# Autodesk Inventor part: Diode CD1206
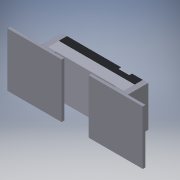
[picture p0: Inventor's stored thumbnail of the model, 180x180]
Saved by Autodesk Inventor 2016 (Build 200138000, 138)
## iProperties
Created: 2018-03
Part Number: Diode CD1206
Material: Générique
Document SubType Name: Modeling
Designer: Bruno
Density: 1 g/cm^3
Appearance: Par défaut
Author: Bruno
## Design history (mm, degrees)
feature "Composite1"
body "Srf1"
